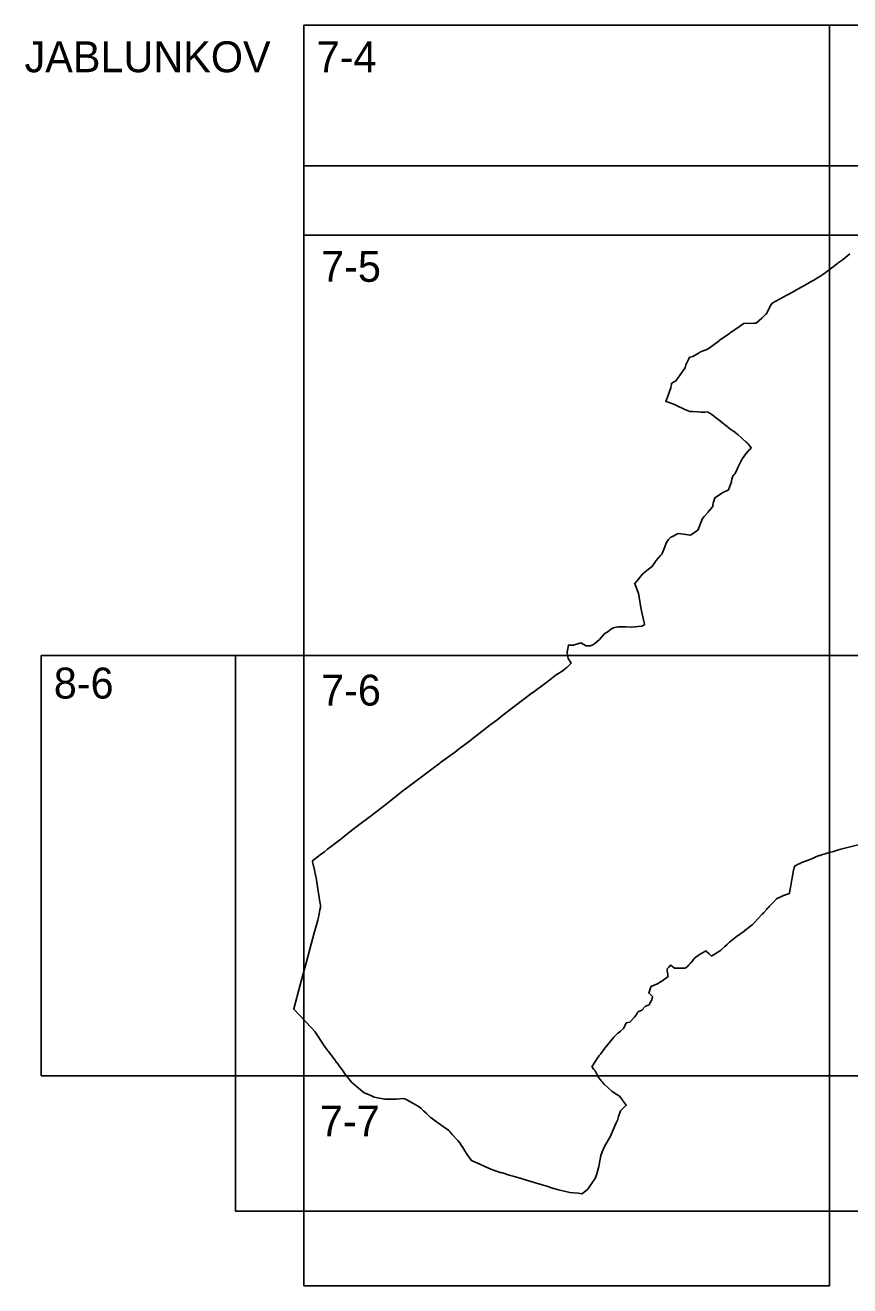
# Model space of a CAD drawing. Extents: x -447352 to -425530, y -1135906 to -1125104.
# Drawn here: x -429458.7 to -429213.6, y -1126693.2 to -1126318.2 of the extents above; entities that cross this region are included whole.
import ezdxf

# ---------------------------------------------------------------- set-up
doc = ezdxf.new("R2010")
doc.units = 0
for name, color, linetype in [('Vrstva 1', 7, 'Continuous'), ('Vrstva 10', 7, 'Continuous'), ('Vrstva 4', 7, 'Continuous')]:
    doc.layers.add(name, color=color, linetype=linetype)

msp = doc.modelspace()

# ---------------------------------------------------------------- linework, layer by layer
at = {"layer": 'Vrstva 1'}
for points in [[(-429213.51, -1126386.26), (-429214.72, -1126387.22), (-429214.72, -1126387.22), (-429215.87, -1126388.09), (-429216.44, -1126388.52), (-429217.02, -1126388.96), (-429217.18, -1126389.08), (-429219.31, -1126390.73), (-429220.38, -1126391.55), (-429220.85, -1126391.88), (-429221.61, -1126392.39), (-429221.86, -1126392.55), (-429222.45, -1126392.95), (-429222.49, -1126392.97), (-429222.7, -1126393.11), (-429223.61, -1126393.71), (-429223.62, -1126393.71), (-429224.09, -1126393.97), (-429224.24, -1126394.06), (-429224.42, -1126394.15), (-429224.88, -1126394.41), (-429225.06, -1126394.51), (-429225.22, -1126394.6), (-429225.32, -1126394.66), (-429225.56, -1126394.8), (-429227.22, -1126395.74), (-429227.39, -1126395.84), (-429227.62, -1126395.96), (-429230.09, -1126397.36), (-429230.21, -1126397.43), (-429232.32, -1126398.57), (-429233.34, -1126399.12), (-429236.68, -1126400.93), (-429236.85, -1126401.22), (-429236.91, -1126401.33), (-429237.69, -1126402.8), (-429238.37, -1126404.12), (-429238.51, -1126404.24), (-429238.6, -1126404.33), (-429239.74, -1126405.37), (-429241.25, -1126406.74), (-429241.42, -1126406.9), (-429241.42, -1126406.9), (-429241.89, -1126406.91), (-429245.08, -1126407), (-429245.09, -1126407), (-429245.52, -1126407.29), (-429246.35, -1126407.86), (-429248.82, -1126409.52), (-429248.86, -1126409.55), (-429249.1, -1126409.72), (-429249.37, -1126409.93), (-429252.35, -1126412.05), (-429252.42, -1126412.1), (-429255.42, -1126414.28), (-429255.89, -1126414.62), (-429256.05, -1126414.68), (-429257.99, -1126415.4), (-429258, -1126415.41), (-429258.39, -1126415.65), (-429260.27, -1126416.8), (-429261.19, -1126417.01), (-429261.44, -1126417.52), (-429262.2, -1126419.03), (-429262.21, -1126419.05), (-429262.28, -1126419.3), (-429262.48, -1126420.14), (-429263.31, -1126421.26), (-429264.68, -1126423.21), (-429265.24, -1126424.01), (-429265.27, -1126424.03), (-429266.43, -1126424.68), (-429266.53, -1126424.73), (-429266.6, -1126425.12), (-429266.75, -1126425.94), (-429266.8, -1126426.12), (-429268.09, -1126429.7), (-429268.26, -1126430.19), (-429268.23, -1126430.17), (-429268.21, -1126430.16), (-429267.53, -1126430.42), (-429265.72, -1126431.08), (-429265.1, -1126431.37), (-429262.81, -1126432.45), (-429262.79, -1126432.46), (-429261.63, -1126432.92), (-429261.16, -1126433.11), (-429261.13, -1126433.11), (-429260.7, -1126433.14), (-429260.56, -1126433.15), (-429260.34, -1126433.17), (-429258.74, -1126433.28), (-429257.7, -1126433.34), (-429256.65, -1126433.31), (-429255.81, -1126433.28), (-429255.8, -1126433.28), (-429255.52, -1126433.43), (-429255.15, -1126433.69), (-429254.6, -1126434.07), (-429254.21, -1126434.35), (-429252.65, -1126435.49), (-429252.48, -1126435.62), (-429251.37, -1126436.53), (-429250.98, -1126436.85), (-429250.8, -1126437), (-429250.05, -1126437.61), (-429249.78, -1126437.84), (-429249.18, -1126438.33), (-429248.96, -1126438.51), (-429248.32, -1126438.94), (-429247.57, -1126439.43), (-429247.54, -1126439.45), (-429246.78, -1126440.13), (-429245.9, -1126440.91), (-429245.46, -1126441.3), (-429244.45, -1126442.18), (-429244.19, -1126442.42), (-429244.14, -1126442.46), (-429244.04, -1126442.57), (-429244.03, -1126442.57), (-429243.94, -1126442.68), (-429243.91, -1126442.71), (-429242.86, -1126443.93), (-429242.87, -1126443.94), (-429243.31, -1126444.43), (-429243.37, -1126444.5), (-429243.94, -1126445.13), (-429244.76, -1126446.19), (-429244.93, -1126446.4), (-429245.49, -1126447.12), (-429245.79, -1126447.65), (-429245.81, -1126447.69), (-429245.82, -1126447.71), (-429245.95, -1126447.99), (-429246.75, -1126449.66), (-429247.06, -1126450.3), (-429247.68, -1126451.59), (-429247.79, -1126451.84), (-429247.8, -1126451.84), (-429247.84, -1126451.87), (-429248.13, -1126452.06), (-429248.21, -1126452.11), (-429248.26, -1126452.2), (-429248.35, -1126452.41), (-429248.44, -1126452.69), (-429248.61, -1126453.25), (-429248.62, -1126453.26), (-429248.74, -1126453.76), (-429248.76, -1126453.83), (-429248.75, -1126453.9), (-429248.74, -1126453.98), (-429248.74, -1126454.04), (-429248.75, -1126454.1), (-429249.63, -1126456.43), (-429249.65, -1126456.47), (-429249.67, -1126456.51), (-429249.68, -1126456.52), (-429250.38, -1126456.83), (-429250.63, -1126456.94), (-429251.1, -1126457.17), (-429253.71, -1126458.86), (-429253.71, -1126458.86), (-429254.08, -1126460.17), (-429254.16, -1126460.44), (-429254.27, -1126460.85), (-429254.33, -1126461.07), (-429254.33, -1126461.07), (-429254.32, -1126461.08), (-429254.15, -1126461.24), (-429254.16, -1126461.24), (-429254.52, -1126461.63), (-429255.32, -1126462.63), (-429255.33, -1126462.64), (-429255.54, -1126462.89), (-429255.54, -1126462.9), (-429255.66, -1126463.05), (-429256.82, -1126464.4), (-429257.36, -1126465.03), (-429258.12, -1126466.98), (-429258.5, -1126468.01), (-429258.63, -1126468.35), (-429260.16, -1126469.45), (-429260.78, -1126469.89), (-429260.96, -1126469.93), (-429260.98, -1126469.94), (-429261.61, -1126469.84), (-429264.45, -1126469.42), (-429264.94, -1126469.66), (-429266.27, -1126470.3), (-429266.81, -1126470.56), (-429266.84, -1126470.59), (-429267.27, -1126471.01), (-429267.44, -1126471.22), (-429268.1, -1126472.08), (-429268.1, -1126472.09), (-429268.77, -1126473.88), (-429269.34, -1126475.39), (-429269.34, -1126475.39), (-429269.48, -1126475.61), (-429269.81, -1126475.98), (-429270.53, -1126476.77), (-429271.23, -1126477.55), (-429271.24, -1126477.56), (-429271.37, -1126477.75), (-429272.44, -1126479.33), (-429272.91, -1126479.7), (-429274.48, -1126480.96), (-429275.15, -1126481.5), (-429275.25, -1126481.59), (-429275.28, -1126481.62), (-429276.4, -1126483.06), (-429277.54, -1126484.37), (-429277.39, -1126484.54), (-429277.38, -1126484.57), (-429277.38, -1126484.57), (-429276.37, -1126487.33), (-429276.09, -1126488.99), (-429275.77, -1126490.94), (-429275.36, -1126492.9), (-429274.63, -1126496.4), (-429274.59, -1126496.6), (-429275.24, -1126496.95), (-429275.36, -1126497.01), (-429278.53, -1126497.27), (-429278.69, -1126497.27), (-429280.18, -1126497.25), (-429282.57, -1126497.22), (-429283.85, -1126497.49), (-429284.45, -1126497.76), (-429285.43, -1126498.56), (-429286.73, -1126499.44), (-429286.82, -1126499.55), (-429287.98, -1126500.96), (-429289.43, -1126502.31), (-429290.12, -1126502.63), (-429290.72, -1126502.9), (-429291.89, -1126502.84), (-429293.5, -1126501.99), (-429295.74, -1126502.66), (-429297.22, -1126502.62), (-429297.6, -1126504.73), (-429297.61, -1126504.75), (-429297.62, -1126504.85), (-429297.33, -1126506.65), (-429296.36, -1126507.97), (-429296.35, -1126507.99), (-429297.09, -1126508.74), (-429297.7, -1126509.31), (-429297.95, -1126509.53), (-429298.75, -1126510.16), (-429300.68, -1126511.39), (-429300.74, -1126511.43), (-429302.71, -1126512.96), (-429302.77, -1126513), (-429303.26, -1126513.38), (-429307.92, -1126516.85), (-429307.95, -1126516.87), (-429312.9, -1126520.64), (-429317.16, -1126523.88), (-429318.04, -1126524.55), (-429320.61, -1126526.49), (-429324.61, -1126529.61), (-429327.05, -1126531.48), (-429330.36, -1126534.02), (-429330.41, -1126534.06), (-429335.2, -1126537.56), (-429335.43, -1126537.74), (-429339.04, -1126540.42), (-429341.43, -1126542.24), (-429343.4, -1126543.72), (-429345.72, -1126545.47), (-429345.95, -1126545.64), (-429347.08, -1126546.54), (-429351.9, -1126550.33), (-429355.79, -1126553.29), (-429360.01, -1126556.53), (-429361.3, -1126557.54), (-429363.69, -1126559.41), (-429364.87, -1126560.33), (-429368.81, -1126563.38), (-429369.74, -1126564.1), (-429370.98, -1126565.06), (-429373.3, -1126566.85), (-429373.3, -1126566.85), (-429373.26, -1126567.03), (-429372.97, -1126568.42), (-429372.94, -1126568.58), (-429372.41, -1126571.11), (-429372.25, -1126571.84), (-429372.25, -1126571.88), (-429371.32, -1126577.77), (-429371.31, -1126577.79), (-429371.01, -1126579.52), (-429371.01, -1126579.54), (-429370.95, -1126579.91), (-429370.89, -1126580.33), (-429370.92, -1126580.71), (-429371.07, -1126581.43), (-429371.45, -1126583.23), (-429371.74, -1126584.4), (-429371.76, -1126584.45), (-429372.87, -1126588.62), (-429374.97, -1126596.51), (-429376.96, -1126603.72), (-429378.89, -1126610.83), (-429378.9, -1126610.86), (-429373.62, -1126616.47), (-429372.57, -1126617.6), (-429371.81, -1126618.81), (-429369.79, -1126621.88), (-429369.74, -1126621.95), (-429368.73, -1126623.36), (-429368.57, -1126623.57), (-429366.69, -1126626.04), (-429366.12, -1126626.79), (-429366.09, -1126626.83), (-429365.57, -1126627.54), (-429364.19, -1126629.44), (-429363.86, -1126629.89), (-429361.71, -1126632.62), (-429360.31, -1126633.83), (-429357.91, -1126635.82), (-429356.17, -1126636.56), (-429354.98, -1126637.08), (-429354.85, -1126637.13), (-429353.52, -1126637.41), (-429353.38, -1126637.44), (-429351.76, -1126637.77), (-429351.73, -1126637.77), (-429350.77, -1126637.76), (-429350.39, -1126637.75), (-429349.87, -1126637.74), (-429349.19, -1126637.73), (-429348.28, -1126637.69), (-429346.33, -1126637.53), (-429345.88, -1126637.6), (-429345.22, -1126637.96), (-429343.5, -1126638.9), (-429341.54, -1126640), (-429341.02, -1126640.48), (-429340.3, -1126641.16), (-429339.5, -1126641.91), (-429338.18, -1126643.21), (-429338.04, -1126643.31), (-429336.85, -1126644.17), (-429334.44, -1126645.87), (-429332.8, -1126647.05), (-429331.75, -1126648.23), (-429330.11, -1126650.05), (-429329.47, -1126650.76), (-429329.11, -1126651.36), (-429328.65, -1126652.09), (-429327.71, -1126653.57), (-429327.08, -1126654.48), (-429326.04, -1126655.93), (-429324.97, -1126656.43), (-429323.59, -1126657.08), (-429322.28, -1126657.7), (-429320.31, -1126658.58), (-429319.18, -1126658.93), (-429317.46, -1126659.51), (-429317.31, -1126659.56), (-429316.22, -1126659.87), (-429314.8, -1126660.29), (-429314.79, -1126660.3), (-429314.58, -1126660.36), (-429314.52, -1126660.38), (-429313.66, -1126660.63), (-429311.27, -1126661.33), (-429311.15, -1126661.36), (-429310.67, -1126661.5), (-429307.74, -1126662.38), (-429305.05, -1126663.2), (-429304.71, -1126663.31), (-429303.95, -1126663.54), (-429301.94, -1126664.15), (-429300.21, -1126664.71), (-429296.75, -1126665.44)], [(-429296.75, -1126665.44), (-429294.36, -1126665.64), (-429293.16, -1126665.87), (-429293.05, -1126665.78), (-429291.47, -1126664.5), (-429290.44, -1126663.02), (-429290.33, -1126662.87), (-429289.81, -1126662.12), (-429289.7, -1126661.94), (-429289.56, -1126661.71), (-429289.18, -1126661.09), (-429288.91, -1126660.25), (-429288.89, -1126660.18), (-429288.87, -1126660.13), (-429288.84, -1126660.03), (-429288.81, -1126659.93), (-429288.81, -1126659.93), (-429288.18, -1126657.72), (-429288.04, -1126657.2), (-429287.59, -1126654.45), (-429287.59, -1126654.45), (-429287.4, -1126654.01), (-429287.14, -1126653.4), (-429286.35, -1126651.56), (-429284.78, -1126648.92), (-429283.03, -1126644.78), (-429282.71, -1126644.14), (-429282.67, -1126644.02), (-429282.28, -1126642.92), (-429281.69, -1126641.24), (-429280.01, -1126639.54), (-429280.94, -1126638.29), (-429281, -1126638.21), (-429281.05, -1126638.14), (-429281.08, -1126638.1), (-429281.15, -1126638.01), (-429281.2, -1126637.93), (-429281.28, -1126637.8), (-429281.64, -1126637.29), (-429282.01, -1126636.82), (-429282.58, -1126636.45), (-429282.68, -1126636.39), (-429284.33, -1126635.32), (-429286.52, -1126633.38), (-429286.65, -1126633.21), (-429286.68, -1126633.17), (-429286.76, -1126633.07), (-429287.1, -1126632.65), (-429287.43, -1126632.25), (-429287.69, -1126631.93), (-429288.17, -1126631.33), (-429288.25, -1126631.23), (-429288.75, -1126630.27), (-429289.04, -1126629.72), (-429289.27, -1126629.29), (-429289.32, -1126629.19), (-429289.36, -1126629.15), (-429289.62, -1126628.85), (-429289.82, -1126628.62), (-429290.08, -1126628.34), (-429290.3, -1126628.09), (-429288.44, -1126625.34), (-429288.35, -1126625.22), (-429288.03, -1126624.78), (-429287.71, -1126624.33), (-429286.38, -1126622.5), (-429283.7, -1126619.24), (-429283.35, -1126618.92), (-429282.64, -1126618.22), (-429282.53, -1126618.13), (-429282.34, -1126617.99), (-429281.74, -1126617.52), (-429280.88, -1126616.67), (-429280.47, -1126615.92), (-429280, -1126615.04), (-429278.95, -1126614.8), (-429277.55, -1126613.37), (-429277.01, -1126612.52), (-429277, -1126612.51), (-429277, -1126612.5), (-429276.79, -1126612.17), (-429276.74, -1126612.08), (-429276.5, -1126611.7), (-429275.34, -1126611.25), (-429274.32, -1126610.07), (-429273.79, -1126609.87), (-429273.67, -1126609.82), (-429273.25, -1126609.66), (-429273.03, -1126609.27), (-429272.98, -1126609.18), (-429272.81, -1126608.88), (-429272.4, -1126608.15), (-429272.2, -1126607.23), (-429272.2, -1126607.22), (-429272.19, -1126607.2), (-429273.24, -1126606.22), (-429273.26, -1126606.2), (-429273.27, -1126606.19), (-429273.32, -1126606.14), (-429272.67, -1126604.34), (-429272.6, -1126604.14), (-429272.44, -1126604.09), (-429271.71, -1126603.8), (-429271.02, -1126603.52), (-429270.9, -1126603.48), (-429269.69, -1126602.76), (-429269.57, -1126602.69), (-429269.57, -1126602.69), (-429269.56, -1126602.68), (-429269.44, -1126602.6), (-429267.58, -1126601.2), (-429267.58, -1126601.16), (-429267.61, -1126601), (-429267.68, -1126600.53), (-429267.74, -1126600.18), (-429267.84, -1126599.55), (-429267.86, -1126599.45), (-429267.88, -1126599.31), (-429267.9, -1126599.14), (-429267.93, -1126599.01), (-429267.39, -1126598.45), (-429266.83, -1126597.87), (-429266.79, -1126597.82), (-429266.65, -1126597.93), (-429265.65, -1126598.71), (-429264.97, -1126598.72), (-429264.91, -1126598.72), (-429264.66, -1126598.73), (-429264.5, -1126598.73), (-429263.19, -1126598.76), (-429262.56, -1126598.77), (-429262.29, -1126598.61), (-429262.26, -1126598.59), (-429262.14, -1126598.52), (-429262, -1126598.43), (-429261.96, -1126598.4), (-429261.42, -1126597.8), (-429261.31, -1126597.68), (-429261.22, -1126597.59), (-429261.05, -1126597.4), (-429260.97, -1126597.31), (-429260.86, -1126597.2), (-429260.83, -1126597.16), (-429260.8, -1126597.12), (-429260.75, -1126597.06), (-429260.66, -1126596.95), (-429260.26, -1126596.45), (-429260.05, -1126596.19), (-429259.8, -1126595.87), (-429259.69, -1126595.79), (-429258.23, -1126594.72), (-429258.02, -1126594.6), (-429256.66, -1126593.82), (-429256.26, -1126593.6), (-429256.26, -1126593.6), (-429256.12, -1126593.75), (-429255.41, -1126594.46), (-429255.04, -1126594.83), (-429254.86, -1126595), (-429254.71, -1126595.16), (-429254.62, -1126595.11), (-429253.34, -1126594.34), (-429253.25, -1126594.29), (-429252.32, -1126593.73), (-429252.28, -1126593.7), (-429251.95, -1126593.41), (-429251.9, -1126593.37), (-429251.73, -1126593.22), (-429251.72, -1126593.21), (-429251.72, -1126593.21), (-429251.68, -1126593.17), (-429251.64, -1126593.13), (-429250.75, -1126592.32), (-429250.73, -1126592.31), (-429250.14, -1126591.77), (-429250.03, -1126591.68), (-429249.92, -1126591.59), (-429249.92, -1126591.59), (-429249.91, -1126591.58), (-429249.91, -1126591.58), (-429249.91, -1126591.58), (-429249.9, -1126591.57), (-429249.89, -1126591.57), (-429249.89, -1126591.56), (-429249.88, -1126591.56), (-429249.88, -1126591.55), (-429249.87, -1126591.55), (-429249.87, -1126591.55), (-429249.29, -1126591.06), (-429247.3, -1126589.39), (-429246.1, -1126588.54), (-429245.98, -1126588.45), (-429245.93, -1126588.42), (-429245.91, -1126588.4), (-429245.86, -1126588.37), (-429245.5, -1126588.11), (-429244.26, -1126587.16), (-429244.08, -1126587.02), (-429243.87, -1126586.86), (-429243.85, -1126586.84), (-429242.97, -1126586.17), (-429242.62, -1126585.9), (-429242.57, -1126585.84), (-429242.48, -1126585.74), (-429241.84, -1126585.06), (-429240.94, -1126584.09), (-429239.58, -1126582.68), (-429239.36, -1126582.44), (-429239.11, -1126582.16), (-429238.27, -1126581.22), (-429237.98, -1126580.89), (-429237.78, -1126580.68), (-429237.49, -1126580.36), (-429236.31, -1126579.17), (-429235.38, -1126578.16), (-429233.32, -1126577.14), (-429233.16, -1126577.09), (-429232.96, -1126577.02), (-429231.52, -1126576.52), (-429231.37, -1126575.65), (-429231.21, -1126574.79), (-429230.79, -1126572.41), (-429230.71, -1126571.95), (-429230.38, -1126570.07), (-429230.18, -1126569.18), (-429230.15, -1126569.06), (-429230.1, -1126568.87), (-429230.09, -1126568.83), (-429230.07, -1126568.77), (-429230.06, -1126568.72), (-429230.05, -1126568.68), (-429230.04, -1126568.64), (-429230.03, -1126568.61), (-429229.97, -1126568.4), (-429228.89, -1126567.86), (-429228.6, -1126567.72), (-429228.58, -1126567.71), (-429228.33, -1126567.59), (-429228.28, -1126567.56), (-429226.51, -1126566.84), (-429226.48, -1126566.83), (-429226.45, -1126566.82), (-429225.65, -1126566.51), (-429224.69, -1126566.1), (-429223.88, -1126565.76), (-429222.94, -1126565.38), (-429222.86, -1126565.34), (-429222.25, -1126565.11), (-429222.4, -1126565.26), (-429222.16, -1126565.18), (-429221.67, -1126564.97), (-429221.14, -1126564.81), (-429219.44, -1126564.29), (-429218.85, -1126564.13), (-429218.4, -1126564), (-429217.51, -1126563.75), (-429216.2, -1126563.37), (-429214.66, -1126562.92), (-429211.12, -1126562.05)]]:
    msp.add_lwpolyline(points, dxfattribs=at)
at = {"layer": 'Vrstva 10'}
msp.add_lwpolyline([(-429063.36, -1126360.06), (-429063.36, -1126671.03), (-429396.23, -1126671.03), (-429396.23, -1126505.74), (-429375.86, -1126505.74), (-429375.86, -1126380.74), (-429375.86, -1126360.06), (-429063.36, -1126360.06)], dxfattribs=at)
at = {"layer": 'Vrstva 4'}
for p, q in [((-429375.86, -1126318.24), (-429063.36, -1126318.24)), ((-429453.99, -1126505.74), (-429453.99, -1126630.74)), ((-429375.86, -1126693.24), (-429219.61, -1126693.24))]:
    msp.add_line(p, q, dxfattribs=at)
for points in [[(-429219.61, -1126318.24), (-429219.61, -1126380.74), (-429375.86, -1126380.74), (-429375.86, -1126318.24)], [(-429063.36, -1126318.24), (-429063.36, -1126380.74), (-429219.61, -1126380.74), (-429219.61, -1126318.24)], [(-429453.99, -1126505.74), (-429375.86, -1126505.74), (-429375.86, -1126630.74), (-429453.99, -1126630.74)], [(-429375.86, -1126693.24), (-429375.86, -1126630.74), (-429219.61, -1126630.74), (-429219.61, -1126693.24)]]:
    msp.add_lwpolyline(points, dxfattribs=at)
for points in [[(-429219.61, -1126380.74), (-429219.61, -1126505.74), (-429375.86, -1126505.74), (-429375.86, -1126380.74)], [(-429063.36, -1126380.74), (-429063.36, -1126505.74), (-429219.61, -1126505.74), (-429219.61, -1126380.74)], [(-429219.61, -1126505.74), (-429219.61, -1126630.74), (-429375.86, -1126630.74), (-429375.86, -1126505.74)], [(-429063.36, -1126505.74), (-429063.36, -1126630.74), (-429219.61, -1126630.74), (-429219.61, -1126505.74)]]:
    msp.add_lwpolyline(points, close=True, dxfattribs=at)

# ---------------------------------------------------------------- texts
at = {"layer": 'Vrstva 1'}
for s, p in [('JABLUNKOV', (-429458.9, -1126332.23)), ('7-4', (-429372.05, -1126332.23)), ('7-5', (-429370.74, -1126394.57)), ('8-6', (-429450.21, -1126518.54)), ('7-6', (-429370.74, -1126520.64)), ('7-7', (-429371.1, -1126648.81))]:
    msp.add_text(s, height=9.2, dxfattribs=at).set_placement(p)

doc.saveas('drawing.dxf')
